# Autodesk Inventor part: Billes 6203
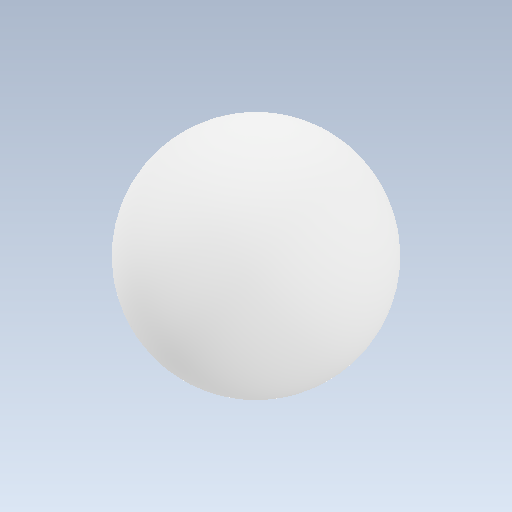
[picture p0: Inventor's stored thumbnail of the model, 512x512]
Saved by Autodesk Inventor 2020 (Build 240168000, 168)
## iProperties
Created: 2003-07
Part Number: Billes 6203
Material: Générique
Document SubType Name: Modeling
Designer: Bruno
Density: 1 g/cm^3
Appearance: Par défaut
Author: Bruno
Sending System: SolidWorks 2011
Last Author: frederic
Last Saved: 2012-02-20
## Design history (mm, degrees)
feature "Base-Révolution"
node "Solide1"
